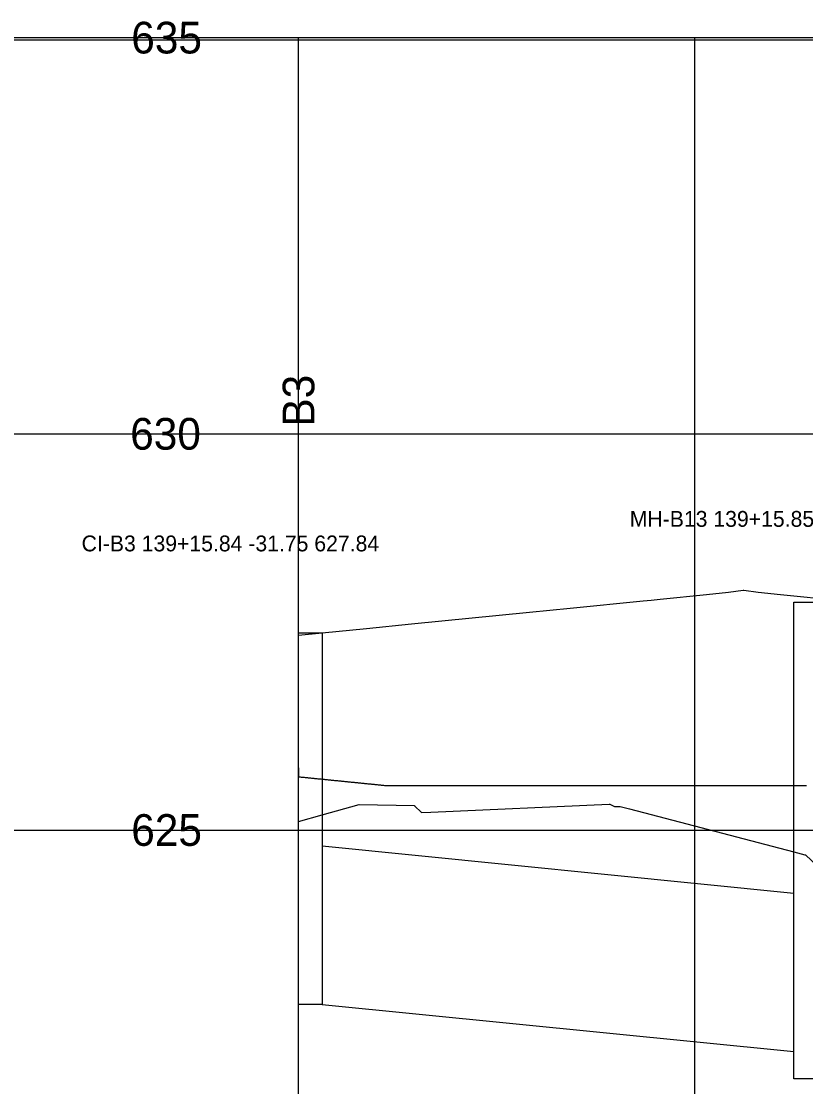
# Model space of a CAD drawing. Extents: x 2253035 to 2279930, y 13774972 to 13793443.
# Drawn here: x 2276931.9 to 2276981.4, y 13792726.4 to 13792793.6 of the extents above; entities that cross this region are included whole.
import ezdxf

# ---------------------------------------------------------------- set-up
doc = ezdxf.new("R2010")
doc.units = 0
for name, color, linetype in [('Default', 7, 'Continuous'), ('E_Utility_ATT_HH', 7, 'Continuous'), ('E_Utility_ATT_PR_PVC', 7, 'Continuous'), ('E_Utility_Telephone_Manhole Telephone_MHT_point', 7, 'Continuous'), ('E_Utility_Telephone_Telephone Pedestal_TPED_Description', 7, 'Continuous'), ('E_Utility_Water_Water Meter_WM_Description', 7, 'Continuous'), ('E_Utillity_Water_Water Line_12in', 7, 'Continuous'), ('E_Utillity_Water_Water Line_1in', 7, 'Continuous'), ('E_Utillity_Water_Water Line_4in', 7, 'Continuous'), ('E_Utillity_Water_Water Line_8in', 7, 'Continuous')]:
    doc.layers.add(name, color=color, linetype=linetype)

msp = doc.modelspace()

# ---------------------------------------------------------------- linework, layer by layer
at = {"layer": 'Default'}
for p, q in [((2276949.404, 13792767.599), (2277015.904, 13792767.599)), ((2276949.404, 13792742.599), (2277015.904, 13792742.599))]:
    msp.add_line(p, q, dxfattribs=at)
msp.add_lwpolyline([(2276949.404, 13792692.599), (2276949.404, 13792792.599), (2277015.904, 13792792.599), (2277015.904, 13792692.599)], close=True, dxfattribs=at)
at = {"layer": 'E_Utility_ATT_PR_PVC'}
msp.add_lwpolyline([(2276949.404, 13792746.52), (2276949.404, 13792745.955), (2276949.413, 13792745.959), (2276949.463, 13792745.954), (2276949.513, 13792745.949), (2276949.563, 13792745.944), (2276949.613, 13792745.939), (2276949.663, 13792745.934), (2276949.713, 13792745.929), (2276949.763, 13792745.924), (2276949.813, 13792745.919), (2276949.863, 13792745.914), (2276949.914, 13792745.909), (2276949.964, 13792745.904), (2276950.014, 13792745.899), (2276950.064, 13792745.893), (2276950.114, 13792745.888), (2276950.164, 13792745.883), (2276950.214, 13792745.878), (2276950.264, 13792745.873), (2276950.314, 13792745.868), (2276950.364, 13792745.863), (2276950.414, 13792745.858), (2276950.464, 13792745.853), (2276950.514, 13792745.848), (2276950.564, 13792745.843), (2276950.614, 13792745.838), (2276950.664, 13792745.833), (2276950.714, 13792745.828), (2276950.765, 13792745.823), (2276950.815, 13792745.818), (2276950.865, 13792745.813), (2276950.915, 13792745.808), (2276950.965, 13792745.803), (2276951.015, 13792745.798), (2276951.065, 13792745.793), (2276951.115, 13792745.788), (2276951.165, 13792745.783), (2276951.215, 13792745.778), (2276951.265, 13792745.773), (2276951.315, 13792745.768), (2276951.365, 13792745.763), (2276951.415, 13792745.758), (2276951.465, 13792745.753), (2276951.515, 13792745.748), (2276951.565, 13792745.743), (2276951.616, 13792745.738), (2276951.666, 13792745.733), (2276951.716, 13792745.728), (2276951.766, 13792745.723), (2276951.816, 13792745.718), (2276951.866, 13792745.713), (2276951.916, 13792745.708), (2276951.966, 13792745.703), (2276952.016, 13792745.698), (2276952.066, 13792745.693), (2276952.116, 13792745.688), (2276952.166, 13792745.683), (2276952.216, 13792745.678), (2276952.266, 13792745.673), (2276952.316, 13792745.668), (2276952.366, 13792745.663), (2276952.416, 13792745.658), (2276952.467, 13792745.653), (2276952.517, 13792745.648), (2276952.567, 13792745.643), (2276952.617, 13792745.638), (2276952.667, 13792745.633), (2276952.717, 13792745.628), (2276952.767, 13792745.623), (2276952.817, 13792745.618), (2276952.867, 13792745.613), (2276952.917, 13792745.608), (2276952.967, 13792745.603), (2276953.017, 13792745.598), (2276953.067, 13792745.593), (2276953.117, 13792745.588), (2276953.167, 13792745.583), (2276953.217, 13792745.578), (2276953.267, 13792745.573), (2276953.318, 13792745.568), (2276953.368, 13792745.563), (2276953.418, 13792745.558), (2276953.468, 13792745.553), (2276953.518, 13792745.548), (2276953.568, 13792745.543), (2276953.618, 13792745.538), (2276953.668, 13792745.533), (2276953.718, 13792745.528), (2276953.768, 13792745.523), (2276953.818, 13792745.518), (2276953.868, 13792745.513), (2276953.918, 13792745.508), (2276953.968, 13792745.503), (2276954.018, 13792745.498), (2276954.068, 13792745.493), (2276954.118, 13792745.488), (2276954.169, 13792745.483), (2276954.219, 13792745.478), (2276954.269, 13792745.473), (2276954.319, 13792745.467), (2276954.369, 13792745.462), (2276954.419, 13792745.457), (2276954.469, 13792745.452), (2276954.519, 13792745.447), (2276954.569, 13792745.442), (2276954.619, 13792745.437), (2276954.669, 13792745.432), (2276954.719, 13792745.427), (2276954.769, 13792745.422), (2276954.819, 13792745.417), (2276954.869, 13792745.412), (2276954.919, 13792745.409), (2276954.969, 13792745.409), (2276955.02, 13792745.409), (2276955.07, 13792745.409), (2276955.12, 13792745.409), (2276955.17, 13792745.409), (2276955.22, 13792745.409), (2276955.27, 13792745.409), (2276955.32, 13792745.409), (2276955.37, 13792745.409), (2276955.42, 13792745.409), (2276955.47, 13792745.409), (2276955.52, 13792745.409), (2276955.57, 13792745.409), (2276955.62, 13792745.409), (2276955.67, 13792745.409), (2276955.72, 13792745.409), (2276955.77, 13792745.409), (2276955.82, 13792745.409), (2276955.871, 13792745.409), (2276955.921, 13792745.409), (2276955.971, 13792745.409), (2276956.021, 13792745.409), (2276956.071, 13792745.409), (2276956.121, 13792745.409), (2276956.171, 13792745.409), (2276956.221, 13792745.409), (2276956.271, 13792745.409), (2276956.321, 13792745.409), (2276956.371, 13792745.409), (2276956.421, 13792745.409), (2276956.471, 13792745.409), (2276956.521, 13792745.409), (2276956.571, 13792745.409), (2276956.621, 13792745.409), (2276956.671, 13792745.409), (2276956.722, 13792745.409), (2276956.772, 13792745.409), (2276956.822, 13792745.409), (2276956.872, 13792745.409), (2276956.922, 13792745.409), (2276956.972, 13792745.409), (2276957.022, 13792745.409), (2276957.072, 13792745.409), (2276957.122, 13792745.409), (2276957.172, 13792745.409), (2276957.222, 13792745.409), (2276957.272, 13792745.409), (2276957.322, 13792745.409), (2276957.372, 13792745.409), (2276957.422, 13792745.409), (2276957.472, 13792745.409), (2276957.522, 13792745.409), (2276957.573, 13792745.409), (2276957.623, 13792745.408), (2276957.673, 13792745.408), (2276957.723, 13792745.408), (2276957.773, 13792745.408), (2276957.823, 13792745.408), (2276957.873, 13792745.408), (2276957.923, 13792745.408), (2276957.973, 13792745.408), (2276958.023, 13792745.408), (2276958.073, 13792745.408), (2276958.123, 13792745.408), (2276958.173, 13792745.408), (2276958.223, 13792745.408), (2276958.273, 13792745.408), (2276958.323, 13792745.408), (2276958.373, 13792745.408), (2276958.424, 13792745.408), (2276958.474, 13792745.408), (2276958.524, 13792745.408), (2276958.574, 13792745.408), (2276958.624, 13792745.408), (2276958.674, 13792745.408), (2276958.724, 13792745.408), (2276958.774, 13792745.408), (2276958.824, 13792745.408), (2276958.874, 13792745.408), (2276958.924, 13792745.408), (2276958.974, 13792745.408), (2276959.024, 13792745.408), (2276959.074, 13792745.408), (2276959.124, 13792745.408), (2276959.174, 13792745.408), (2276959.224, 13792745.408), (2276959.275, 13792745.408), (2276959.325, 13792745.408), (2276959.375, 13792745.408), (2276959.425, 13792745.408), (2276959.475, 13792745.408), (2276959.525, 13792745.408), (2276959.575, 13792745.408), (2276959.625, 13792745.408), (2276959.675, 13792745.408), (2276959.725, 13792745.408), (2276959.775, 13792745.408), (2276959.825, 13792745.408), (2276959.875, 13792745.408), (2276959.925, 13792745.408), (2276959.975, 13792745.408), (2276960.025, 13792745.408), (2276960.075, 13792745.408), (2276960.126, 13792745.408), (2276960.176, 13792745.408), (2276960.226, 13792745.408), (2276960.276, 13792745.408), (2276960.326, 13792745.408), (2276960.376, 13792745.408), (2276960.426, 13792745.408), (2276960.476, 13792745.408), (2276960.526, 13792745.408), (2276960.576, 13792745.408), (2276960.626, 13792745.408), (2276960.676, 13792745.408), (2276960.726, 13792745.408), (2276960.776, 13792745.408), (2276960.826, 13792745.408), (2276960.876, 13792745.408), (2276960.926, 13792745.408), (2276960.977, 13792745.408), (2276961.027, 13792745.408), (2276961.077, 13792745.408), (2276961.127, 13792745.408), (2276961.177, 13792745.408), (2276961.227, 13792745.408), (2276961.277, 13792745.408), (2276961.327, 13792745.408), (2276961.377, 13792745.408), (2276961.427, 13792745.408), (2276961.477, 13792745.408), (2276961.527, 13792745.408), (2276961.577, 13792745.408), (2276961.627, 13792745.408), (2276961.677, 13792745.408), (2276961.727, 13792745.408), (2276961.777, 13792745.408), (2276961.828, 13792745.408), (2276961.878, 13792745.408), (2276961.928, 13792745.408), (2276961.978, 13792745.408), (2276962.028, 13792745.408), (2276962.078, 13792745.408), (2276962.128, 13792745.408), (2276962.178, 13792745.408), (2276962.228, 13792745.408), (2276962.278, 13792745.408), (2276962.328, 13792745.408), (2276962.378, 13792745.408), (2276962.428, 13792745.408), (2276962.478, 13792745.408), (2276962.528, 13792745.408), (2276962.578, 13792745.408), (2276962.628, 13792745.408), (2276962.679, 13792745.408), (2276962.729, 13792745.408), (2276962.779, 13792745.408), (2276962.829, 13792745.408), (2276962.879, 13792745.408), (2276962.929, 13792745.408), (2276962.979, 13792745.408), (2276963.029, 13792745.408), (2276963.079, 13792745.408), (2276963.129, 13792745.408), (2276963.179, 13792745.408), (2276963.229, 13792745.408), (2276963.279, 13792745.408), (2276963.329, 13792745.408), (2276963.379, 13792745.408), (2276963.429, 13792745.408), (2276963.479, 13792745.408), (2276963.53, 13792745.408), (2276963.58, 13792745.408), (2276963.63, 13792745.408), (2276963.68, 13792745.408), (2276963.73, 13792745.408), (2276963.78, 13792745.408), (2276963.83, 13792745.408), (2276963.88, 13792745.408), (2276963.93, 13792745.408), (2276963.98, 13792745.408), (2276964.03, 13792745.408), (2276964.08, 13792745.408), (2276964.13, 13792745.408), (2276964.18, 13792745.408), (2276964.23, 13792745.408), (2276964.28, 13792745.408), (2276964.33, 13792745.408), (2276964.381, 13792745.408), (2276964.431, 13792745.408), (2276964.481, 13792745.408), (2276964.531, 13792745.408), (2276964.581, 13792745.408), (2276964.631, 13792745.408), (2276964.681, 13792745.408), (2276964.731, 13792745.408), (2276964.781, 13792745.408), (2276964.831, 13792745.408), (2276964.881, 13792745.408), (2276964.931, 13792745.408), (2276964.981, 13792745.408), (2276965.031, 13792745.408), (2276965.081, 13792745.408), (2276965.131, 13792745.408), (2276965.181, 13792745.408), (2276965.232, 13792745.408), (2276965.282, 13792745.408), (2276965.332, 13792745.408), (2276965.382, 13792745.408), (2276965.432, 13792745.408), (2276965.482, 13792745.408), (2276965.532, 13792745.408), (2276965.582, 13792745.408), (2276965.632, 13792745.408), (2276965.682, 13792745.408), (2276965.732, 13792745.408), (2276965.782, 13792745.408), (2276965.832, 13792745.408), (2276965.882, 13792745.408), (2276965.932, 13792745.408), (2276965.982, 13792745.408), (2276966.032, 13792745.408), (2276966.083, 13792745.408), (2276966.133, 13792745.408), (2276966.183, 13792745.407), (2276966.233, 13792745.407), (2276966.283, 13792745.407), (2276966.333, 13792745.407), (2276966.383, 13792745.407), (2276966.433, 13792745.407), (2276966.483, 13792745.407), (2276966.533, 13792745.407), (2276966.583, 13792745.407), (2276966.633, 13792745.407), (2276966.683, 13792745.407), (2276966.733, 13792745.407), (2276966.783, 13792745.407), (2276966.833, 13792745.407), (2276966.883, 13792745.407), (2276966.934, 13792745.407), (2276966.984, 13792745.407), (2276967.034, 13792745.407), (2276967.084, 13792745.407), (2276967.134, 13792745.407), (2276967.184, 13792745.407), (2276967.234, 13792745.407), (2276967.284, 13792745.407), (2276967.334, 13792745.407), (2276967.384, 13792745.407), (2276967.434, 13792745.407), (2276967.484, 13792745.407), (2276967.534, 13792745.407), (2276967.584, 13792745.407), (2276967.634, 13792745.407), (2276967.684, 13792745.407), (2276967.734, 13792745.407), (2276967.785, 13792745.407), (2276967.835, 13792745.407), (2276967.885, 13792745.407), (2276967.935, 13792745.407), (2276967.985, 13792745.407), (2276968.035, 13792745.407), (2276968.085, 13792745.407), (2276968.135, 13792745.407), (2276968.185, 13792745.407), (2276968.235, 13792745.407), (2276968.285, 13792745.407), (2276968.335, 13792745.407), (2276968.385, 13792745.407), (2276968.435, 13792745.407), (2276968.485, 13792745.407), (2276968.535, 13792745.407), (2276968.585, 13792745.407), (2276968.636, 13792745.407), (2276968.686, 13792745.407), (2276968.736, 13792745.407), (2276968.786, 13792745.407), (2276968.836, 13792745.407), (2276968.886, 13792745.407), (2276968.936, 13792745.407), (2276968.986, 13792745.407), (2276969.036, 13792745.407), (2276969.086, 13792745.407), (2276969.136, 13792745.407), (2276969.186, 13792745.407), (2276969.236, 13792745.407), (2276969.286, 13792745.407), (2276969.336, 13792745.407), (2276969.386, 13792745.407), (2276969.436, 13792745.407), (2276969.487, 13792745.407), (2276969.537, 13792745.407), (2276969.587, 13792745.407), (2276969.637, 13792745.407), (2276969.687, 13792745.407), (2276969.737, 13792745.407), (2276969.787, 13792745.407), (2276969.837, 13792745.407), (2276969.887, 13792745.407), (2276969.937, 13792745.407), (2276969.987, 13792745.407), (2276970.037, 13792745.407), (2276970.087, 13792745.407), (2276970.137, 13792745.407), (2276970.187, 13792745.407), (2276970.237, 13792745.407), (2276970.287, 13792745.407), (2276970.338, 13792745.407), (2276970.388, 13792745.407), (2276970.438, 13792745.407), (2276970.488, 13792745.407), (2276970.538, 13792745.407), (2276970.588, 13792745.407), (2276970.638, 13792745.407), (2276970.688, 13792745.407), (2276970.738, 13792745.407), (2276970.788, 13792745.407), (2276970.838, 13792745.407), (2276970.888, 13792745.407), (2276970.938, 13792745.407), (2276970.988, 13792745.407), (2276971.038, 13792745.407), (2276971.088, 13792745.407), (2276971.138, 13792745.407), (2276971.189, 13792745.407), (2276971.239, 13792745.407), (2276971.289, 13792745.407), (2276971.339, 13792745.407), (2276971.389, 13792745.407), (2276971.439, 13792745.407), (2276971.489, 13792745.407), (2276971.539, 13792745.407), (2276971.589, 13792745.407), (2276971.639, 13792745.407), (2276971.689, 13792745.407), (2276971.739, 13792745.407), (2276971.789, 13792745.407), (2276971.839, 13792745.407), (2276971.889, 13792745.407), (2276971.939, 13792745.407), (2276971.989, 13792745.407), (2276972.04, 13792745.407), (2276972.09, 13792745.407), (2276972.14, 13792745.407), (2276972.19, 13792745.407), (2276972.24, 13792745.407), (2276972.29, 13792745.407), (2276972.34, 13792745.407), (2276972.39, 13792745.407), (2276972.44, 13792745.407), (2276972.49, 13792745.407), (2276972.54, 13792745.407), (2276972.59, 13792745.407), (2276972.64, 13792745.407), (2276972.69, 13792745.407), (2276972.74, 13792745.407), (2276972.79, 13792745.407), (2276972.84, 13792745.407), (2276972.891, 13792745.407), (2276972.941, 13792745.407), (2276972.991, 13792745.407), (2276973.041, 13792745.407), (2276973.091, 13792745.407), (2276973.141, 13792745.407), (2276973.191, 13792745.407), (2276973.241, 13792745.407), (2276973.291, 13792745.407), (2276973.341, 13792745.407), (2276973.391, 13792745.407), (2276973.441, 13792745.407), (2276973.491, 13792745.407), (2276973.541, 13792745.407), (2276973.591, 13792745.407), (2276973.641, 13792745.407), (2276973.691, 13792745.407), (2276973.742, 13792745.407), (2276973.792, 13792745.407), (2276973.842, 13792745.407), (2276973.892, 13792745.407), (2276973.942, 13792745.407), (2276973.992, 13792745.407), (2276974.042, 13792745.407), (2276974.092, 13792745.407), (2276974.142, 13792745.407), (2276974.192, 13792745.407), (2276974.242, 13792745.407), (2276974.292, 13792745.407), (2276974.342, 13792745.407), (2276974.392, 13792745.407), (2276974.442, 13792745.407), (2276974.492, 13792745.407), (2276974.542, 13792745.407), (2276974.593, 13792745.407), (2276974.643, 13792745.407), (2276974.693, 13792745.407), (2276974.743, 13792745.406), (2276974.793, 13792745.406), (2276974.843, 13792745.406), (2276974.893, 13792745.406), (2276974.943, 13792745.406), (2276974.993, 13792745.406), (2276975.043, 13792745.406), (2276975.093, 13792745.406), (2276975.143, 13792745.406), (2276975.193, 13792745.406), (2276975.243, 13792745.406), (2276975.293, 13792745.406), (2276975.343, 13792745.406), (2276975.393, 13792745.406), (2276975.444, 13792745.406), (2276975.494, 13792745.406), (2276975.544, 13792745.406), (2276975.594, 13792745.406), (2276975.644, 13792745.406), (2276975.694, 13792745.406), (2276975.744, 13792745.406), (2276975.794, 13792745.406), (2276975.844, 13792745.406), (2276975.894, 13792745.406), (2276975.944, 13792745.406), (2276975.994, 13792745.406), (2276976.044, 13792745.406), (2276976.094, 13792745.406), (2276976.144, 13792745.406), (2276976.194, 13792745.406), (2276976.244, 13792745.406), (2276976.295, 13792745.406), (2276976.345, 13792745.406), (2276976.395, 13792745.406), (2276976.445, 13792745.406), (2276976.495, 13792745.406), (2276976.545, 13792745.406), (2276976.595, 13792745.406), (2276976.645, 13792745.406), (2276976.695, 13792745.406), (2276976.745, 13792745.406), (2276976.795, 13792745.406), (2276976.845, 13792745.406), (2276976.895, 13792745.406), (2276976.945, 13792745.406), (2276976.995, 13792745.406), (2276977.045, 13792745.406), (2276977.095, 13792745.406), (2276977.146, 13792745.406), (2276977.196, 13792745.406), (2276977.246, 13792745.406), (2276977.296, 13792745.406), (2276977.346, 13792745.406), (2276977.396, 13792745.406), (2276977.446, 13792745.406), (2276977.496, 13792745.406), (2276977.546, 13792745.406), (2276977.596, 13792745.406), (2276977.646, 13792745.406), (2276977.696, 13792745.406), (2276977.746, 13792745.406), (2276977.796, 13792745.406), (2276977.846, 13792745.406), (2276977.896, 13792745.406), (2276977.946, 13792745.406), (2276977.997, 13792745.406), (2276978.047, 13792745.406), (2276978.097, 13792745.406), (2276978.147, 13792745.406), (2276978.197, 13792745.406), (2276978.247, 13792745.406), (2276978.297, 13792745.406), (2276978.347, 13792745.406), (2276978.397, 13792745.406), (2276978.447, 13792745.406), (2276978.497, 13792745.406), (2276978.547, 13792745.406), (2276978.597, 13792745.406), (2276978.647, 13792745.406), (2276978.697, 13792745.406), (2276978.747, 13792745.406), (2276978.797, 13792745.406), (2276978.848, 13792745.406), (2276978.898, 13792745.406), (2276978.948, 13792745.406), (2276978.998, 13792745.406), (2276979.048, 13792745.406), (2276979.098, 13792745.406), (2276979.148, 13792745.406), (2276979.198, 13792745.406), (2276979.248, 13792745.406), (2276979.298, 13792745.406), (2276979.348, 13792745.406), (2276979.398, 13792745.406), (2276979.448, 13792745.406), (2276979.498, 13792745.406), (2276979.548, 13792745.406), (2276979.598, 13792745.406), (2276979.649, 13792745.406), (2276979.699, 13792745.406), (2276979.749, 13792745.406), (2276979.799, 13792745.406), (2276979.849, 13792745.406), (2276979.899, 13792745.406), (2276979.949, 13792745.406), (2276979.999, 13792745.406), (2276980.049, 13792745.406), (2276980.099, 13792745.406), (2276980.149, 13792745.406), (2276980.199, 13792745.406), (2276980.249, 13792745.406), (2276980.299, 13792745.406), (2276980.349, 13792745.406), (2276980.399, 13792745.406), (2276980.449, 13792745.406), (2276980.5, 13792745.406), (2276980.55, 13792745.406), (2276980.6, 13792745.406), (2276980.65, 13792745.406), (2276980.7, 13792745.406), (2276980.75, 13792745.406), (2276980.8, 13792745.406), (2276980.85, 13792745.406), (2276980.9, 13792745.406), (2276980.95, 13792745.406), (2276981, 13792745.406), (2276981.05, 13792745.406), (2276981.1, 13792745.406), (2276981.15, 13792745.406), (2276981.2, 13792745.406), (2276981.25, 13792745.406), (2276981.3, 13792745.406), (2276981.351, 13792745.406), (2276981.401, 13792745.406), (2276981.451, 13792745.406)], dxfattribs=at)
at = {"layer": 'E_Utility_Telephone_Manhole Telephone_MHT_point'}
for p, q in [((2276749.404, 13792792.599), (2277074.404, 13792792.599)), ((2276949.404, 13792492.599), (2276949.404, 13792792.599)), ((2276974.404, 13792492.599), (2276974.404, 13792792.599)), ((2276749.404, 13792767.599), (2277074.404, 13792767.599)), ((2276749.404, 13792742.599), (2277074.404, 13792742.599))]:
    msp.add_line(p, q, dxfattribs=at)
at = {"layer": 'E_Utility_Water_Water Meter_WM_Description'}
msp.add_lwpolyline([(2277133.026, 13792792.439), (2276749.404, 13792792.439), (2276749.404, 13792491.266), (2277133.026, 13792491.266)], close=True, dxfattribs=at)
at = {"layer": 'E_Utillity_Water_Water Line_12in'}
for points in [[(2276980.654, 13792756.975), (2276988.654, 13792756.975), (2276988.654, 13792726.899), (2276980.654, 13792726.899)], [(2276949.404, 13792755.036), (2276950.904, 13792755.036), (2276950.904, 13792731.599), (2276949.404, 13792731.599)]]:
    msp.add_lwpolyline(points, close=True, dxfattribs=at)
at = {"layer": 'E_Utillity_Water_Water Line_1in'}
msp.add_lwpolyline([(2276949.404, 13792743.132), (2276950.904, 13792743.554), (2276950.904, 13792743.554), (2276953.227, 13792744.208), (2276956.716, 13792744.152), (2276956.731, 13792744.123), (2276957.154, 13792743.695), (2276957.756, 13792743.721), (2276969.004, 13792744.237), (2276969.04, 13792744.234), (2276969.347, 13792744.092), (2276969.695, 13792744.092), (2276970.297, 13792743.931), (2276980.654, 13792741.221), (2276980.654, 13792741.221), (2276981.35, 13792741.039), (2276981.383, 13792741.039), (2276984.654, 13792737.969)], dxfattribs=at)
at = {"layer": 'E_Utillity_Water_Water Line_4in'}
for p, q in [((2276950.904, 13792741.599), (2276980.654, 13792738.624)), ((2276950.904, 13792731.599), (2276980.654, 13792728.624))]:
    msp.add_line(p, q, dxfattribs=at)
at = {"layer": 'E_Utillity_Water_Water Line_8in'}
msp.add_lwpolyline([(2276949.404, 13792754.886), (2276950.904, 13792755.036), (2276950.904, 13792755.036), (2276953.69, 13792755.314), (2276956.535, 13792755.599), (2276963.969, 13792756.342), (2276966.535, 13792756.599), (2276971.146, 13792757.06), (2276971.649, 13792757.11), (2276972.223, 13792757.167), (2276975.141, 13792757.459), (2276976.536, 13792757.599), (2276977.452, 13792757.723), (2276977.496, 13792757.723), (2276978.412, 13792757.599), (2276979.81, 13792757.459), (2276980.654, 13792757.374), (2276980.654, 13792757.374), (2276982.743, 13792757.166)], dxfattribs=at)

# ---------------------------------------------------------------- texts
at = {"layer": 'Default'}
for s, p in [('635', (2276938.848, 13792791.599)), ('630', (2276938.782, 13792766.599)), ('625', (2276938.848, 13792741.599))]:
    msp.add_text(s, height=2, dxfattribs=at).set_placement(p)
at = {"layer": 'E_Utility_ATT_HH'}
msp.add_text('B3', height=2, rotation=90, dxfattribs=at).set_placement((2276950.404, 13792768.052))
at = {"layer": 'E_Utility_Telephone_Telephone Pedestal_TPED_Description'}
for s, p in [('MH-B13 139+15.85 2.00 627.98', (2276970.303, 13792761.731)), ('CI-B3 139+15.84 -31.75 627.84', (2276935.717, 13792760.182))]:
    msp.add_text(s, height=1, rotation=0, dxfattribs=at).set_placement(p)

doc.saveas('drawing.dxf')
